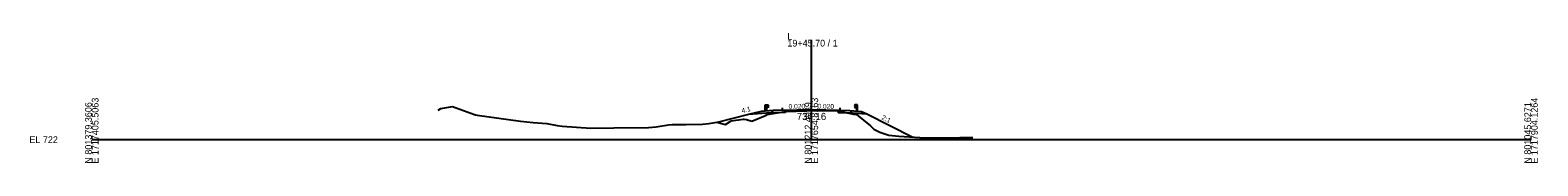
# Model space of a CAD drawing. Extents: x 974 to 5203, y -10 to 9544.
# Drawn here: x 974 to 1603, y 9490 to 9544 of the extents above; entities that cross this region are included whole.
import ezdxf

# ---------------------------------------------------------------- set-up
doc = ezdxf.new("R2010")
doc.units = 0
for name, color, linetype in [('Exist Cross Section Cell', 7, 'Continuous'), ('Exist XS Center Line Elevation Label', 7, 'Continuous'), ('Exist XS Ground Line', 7, 'Continuous'), ('Prop XS Dump Level', 7, 'Continuous'), ('Prop XS EOT Tick Mark', 7, 'Continuous'), ('Prop XS Finish Grade', 7, 'Continuous'), ('Prop XS Finish Grade Earthwork', 7, 'Continuous'), ('Prop XS Finish Grade Paved Shoulder', 7, 'Continuous'), ('Prop XS Finish Grade Pavement', 7, 'Continuous'), ('Prop XS Guardrail', 7, 'Continuous'), ('Prop XS Pvmt Edge Slope', 7, 'Continuous'), ('Prop XS SE Text', 7, 'Continuous'), ('Prop XS Side Slope Text', 7, 'Continuous'), ('Prop XS Subgrade Earthwork', 7, 'Continuous')]:
    doc.layers.add(name, color=color, linetype=linetype)

msp = doc.modelspace()

# ---------------------------------------------------------------- linework, layer by layer
at = {"layer": 'Exist Cross Section Cell'}
for p, q in [((1300, 9500), (1300, 9541.62)), ((1000, 9500), (1300, 9500)), ((1300, 9500), (1600, 9500))]:
    msp.add_line(p, q, dxfattribs=at)
at = {"layer": 'Exist XS Ground Line'}
for p, q in [((1144.46, 9512.32), (1145.46, 9512.96)), ((1145.46, 9512.96), (1150.4, 9513.87)), ((1150.4, 9513.87), (1159.6, 9510.55)), ((1159.6, 9510.55), (1160.03, 9510.39)), ((1160.03, 9510.39), (1160.68, 9510.26)), ((1160.68, 9510.26), (1178.72, 9507.75)), ((1276.8, 9508.35), (1280.8, 9510.12)), ((1280.8, 9510.12), (1281.53, 9510.43)), ((1281.53, 9510.43), (1282.41, 9510.57)), ((1282.41, 9510.57), (1289.18, 9511.71)), ((1289.18, 9511.71), (1298.15, 9512.08)), ((1298.15, 9512.08), (1299.83, 9512.17)), ((1299.83, 9512.17), (1301.66, 9512.14)), ((1301.66, 9512.14), (1311.19, 9512.03)), ((1311.19, 9512.03), (1313.71, 9511.47)), ((1313.71, 9511.47), (1317.56, 9510.57)), ((1317.56, 9510.57), (1318.78, 9510.5)), ((1318.78, 9510.5), (1324.6, 9505.73)), ((1178.72, 9507.75), (1183.94, 9507.21)), ((1183.94, 9507.21), (1189.69, 9506.71)), ((1189.69, 9506.71), (1193.95, 9505.96)), ((1193.95, 9505.96), (1196.04, 9505.68)), ((1196.04, 9505.68), (1207.99, 9504.85)), ((1207.99, 9504.85), (1217.58, 9504.88)), ((1217.58, 9504.88), (1232.14, 9505.12)), ((1232.14, 9505.12), (1235.23, 9505.32)), ((1235.23, 9505.32), (1240.45, 9506.18)), ((1240.45, 9506.18), (1242, 9506.32)), ((1242, 9506.32), (1247.83, 9506.3)), ((1247.83, 9506.3), (1254.59, 9506.39)), ((1254.59, 9506.39), (1257.28, 9506.69)), ((1257.28, 9506.69), (1260.61, 9507.24)), ((1260.61, 9507.24), (1263.62, 9506.41)), ((1263.62, 9506.41), (1264.14, 9506.25)), ((1264.14, 9506.25), (1266.52, 9507.89)), ((1266.52, 9507.89), (1271.54, 9508.51)), ((1271.54, 9508.51), (1271.94, 9508.53)), ((1271.94, 9508.53), (1272.88, 9508.37)), ((1272.88, 9508.37), (1275.12, 9507.77)), ((1275.12, 9507.77), (1276.8, 9508.35)), ((1324.6, 9505.73), (1326.02, 9504.42)), ((1326.02, 9504.42), (1328.53, 9503.11)), ((1328.53, 9503.11), (1332.32, 9501.81)), ((1332.32, 9501.81), (1336.5, 9501.49)), ((1336.5, 9501.49), (1347.42, 9500.74)), ((1347.42, 9500.74), (1352.45, 9500.77)), ((1352.45, 9500.77), (1361.84, 9500.88)), ((1361.84, 9500.88), (1367.34, 9500.86))]:
    msp.add_line(p, q, dxfattribs=at)
at = {"layer": 'Prop XS Dump Level'}
for p, q in [((1288, 9512.26), (1300, 9512.5)), ((1300, 9512.5), (1312, 9512.26))]:
    msp.add_line(p, q, dxfattribs=at)
at = {"layer": 'Prop XS EOT Tick Mark'}
for p, q in [((1288, 9512.26), (1288, 9513.26)), ((1312, 9512.26), (1312, 9513.26))]:
    msp.add_line(p, q, dxfattribs=at)
at = {"layer": 'Prop XS Finish Grade'}
for p, q in [((1279.08, 9511.78), (1273.78, 9510.46)), ((1284, 9512.18), (1279.08, 9511.78)), ((1316, 9512.18), (1320.92, 9511.78)), ((1320.92, 9511.78), (1323.07, 9510.71))]:
    msp.add_line(p, q, dxfattribs=at)
at = {"layer": 'Prop XS Finish Grade Earthwork'}
for p, q in [((1273.78, 9510.46), (1260.74, 9507.2)), ((1323.07, 9510.71), (1342.3, 9501.09))]:
    msp.add_line(p, q, dxfattribs=at)
at = {"layer": 'Prop XS Finish Grade Paved Shoulder'}
for p, q in [((1288, 9512.26), (1284, 9512.18)), ((1312, 9512.26), (1316, 9512.18))]:
    msp.add_line(p, q, dxfattribs=at)
at = {"layer": 'Prop XS Finish Grade Pavement'}
for p, q in [((1288, 9512.26), (1300, 9512.5)), ((1300, 9512.5), (1312, 9512.26))]:
    msp.add_line(p, q, dxfattribs=at)
at = {"layer": 'Prop XS Guardrail'}
for p, q in [((1280.76, 9514.52), (1281.26, 9514.52)), ((1280.76, 9511.92), (1280.76, 9514.52)), ((1281.26, 9514.52), (1281.76, 9514.52)), ((1281.26, 9514.52), (1281.26, 9511.96)), ((1281.76, 9513.39), (1281.26, 9513.39)), ((1281.76, 9514.52), (1282.05, 9514.32)), ((1282.05, 9514.2), (1281.76, 9514)), ((1281.76, 9514), (1281.76, 9513.91)), ((1281.76, 9513.91), (1282.05, 9513.71)), ((1282.05, 9513.59), (1281.76, 9513.39)), ((1282.05, 9514.32), (1282.08, 9514.26)), ((1282.08, 9514.26), (1282.05, 9514.2)), ((1282.05, 9513.71), (1282.08, 9513.65)), ((1282.08, 9513.65), (1282.05, 9513.59)), ((1317.95, 9514.32), (1317.92, 9514.26)), ((1317.92, 9514.26), (1317.95, 9514.2)), ((1317.95, 9513.71), (1317.92, 9513.65)), ((1317.92, 9513.65), (1317.95, 9513.59)), ((1318.24, 9514.52), (1317.95, 9514.32)), ((1317.95, 9514.2), (1318.24, 9514)), ((1318.24, 9513.91), (1317.95, 9513.71)), ((1317.95, 9513.59), (1318.24, 9513.39)), ((1318.74, 9514.52), (1318.24, 9514.52)), ((1318.24, 9514), (1318.24, 9513.91)), ((1318.24, 9513.39), (1318.74, 9513.39)), ((1319.24, 9514.52), (1318.74, 9514.52)), ((1318.74, 9514.52), (1318.74, 9512.02)), ((1319.24, 9512.02), (1319.24, 9514.52))]:
    msp.add_line(p, q, dxfattribs=at)
at = {"layer": 'Prop XS Pvmt Edge Slope'}
for p, q in [((1284, 9512.18), (1283.02, 9511.2)), ((1316, 9512.18), (1316.98, 9511.2))]:
    msp.add_line(p, q, dxfattribs=at)
at = {"layer": 'Prop XS Subgrade Earthwork'}
for p, q in [((1283.02, 9511.2), (1273.78, 9510.46)), ((1289.19, 9511.32), (1283.02, 9511.2)), ((1289.18, 9511.6), (1289.19, 9511.32)), ((1311.19, 9511.31), (1311.19, 9511.92)), ((1311.19, 9511.31), (1316.98, 9511.2)), ((1316.98, 9511.2), (1323.07, 9510.71))]:
    msp.add_line(p, q, dxfattribs=at)

# ---------------------------------------------------------------- texts
at = {"layer": 'Exist Cross Section Cell'}
for s, p in [('19+45.70 / 1', (1290, 9538.82)), ('L', (1290, 9541.62)), ('EL 722', (974, 9498.6))]:
    msp.add_text(s, height=2.8, dxfattribs=at).set_placement(p)
for s, p in [('E 1717405.5063', (1002.8, 9490)), ('E 1717654.8163', (1302.8, 9490)), ('E 1717904.1264', (1602.8, 9490)), ('N 801379.3606', (1000, 9490)), ('N 801212.4939', (1300, 9490)), ('N 801045.6271', (1600, 9490))]:
    msp.add_text(s, height=2.8, rotation=90, dxfattribs=at).set_placement(p)
at = {"layer": 'Exist XS Center Line Elevation Label'}
msp.add_text('734.16', height=3, dxfattribs=at).set_placement((1293.9, 9508.16))
at = {"layer": 'Prop XS Dump Level'}
for s, height, p in [('Case2', 0.04, (1282, 9511.98)), ('Eop', 0.3, (1289.18, 9511.3)), ('Eop', 0.3, (1311.19, 9511.62)), ('Case2', 0.04, (1318, 9511.98))]:
    msp.add_text(s, height=height, dxfattribs=at).set_placement(p)
at = {"layer": 'Prop XS SE Text'}
for rotation, p in [(1.14576, (1290.49, 9512.81)), (358.85424, (1302.49, 9512.95))]:
    msp.add_text('0.020', height=2, rotation=rotation, dxfattribs=at).set_placement(p)
at = {"layer": 'Prop XS Side Slope Text'}
for s, rotation, p in [('4:1', 14.03624, (1271.14, 9511.02)), ('2:1', 333.43495, (1329.04, 9508.59))]:
    msp.add_text(s, height=2, rotation=rotation, dxfattribs=at).set_placement(p)

doc.saveas('drawing.dxf')
